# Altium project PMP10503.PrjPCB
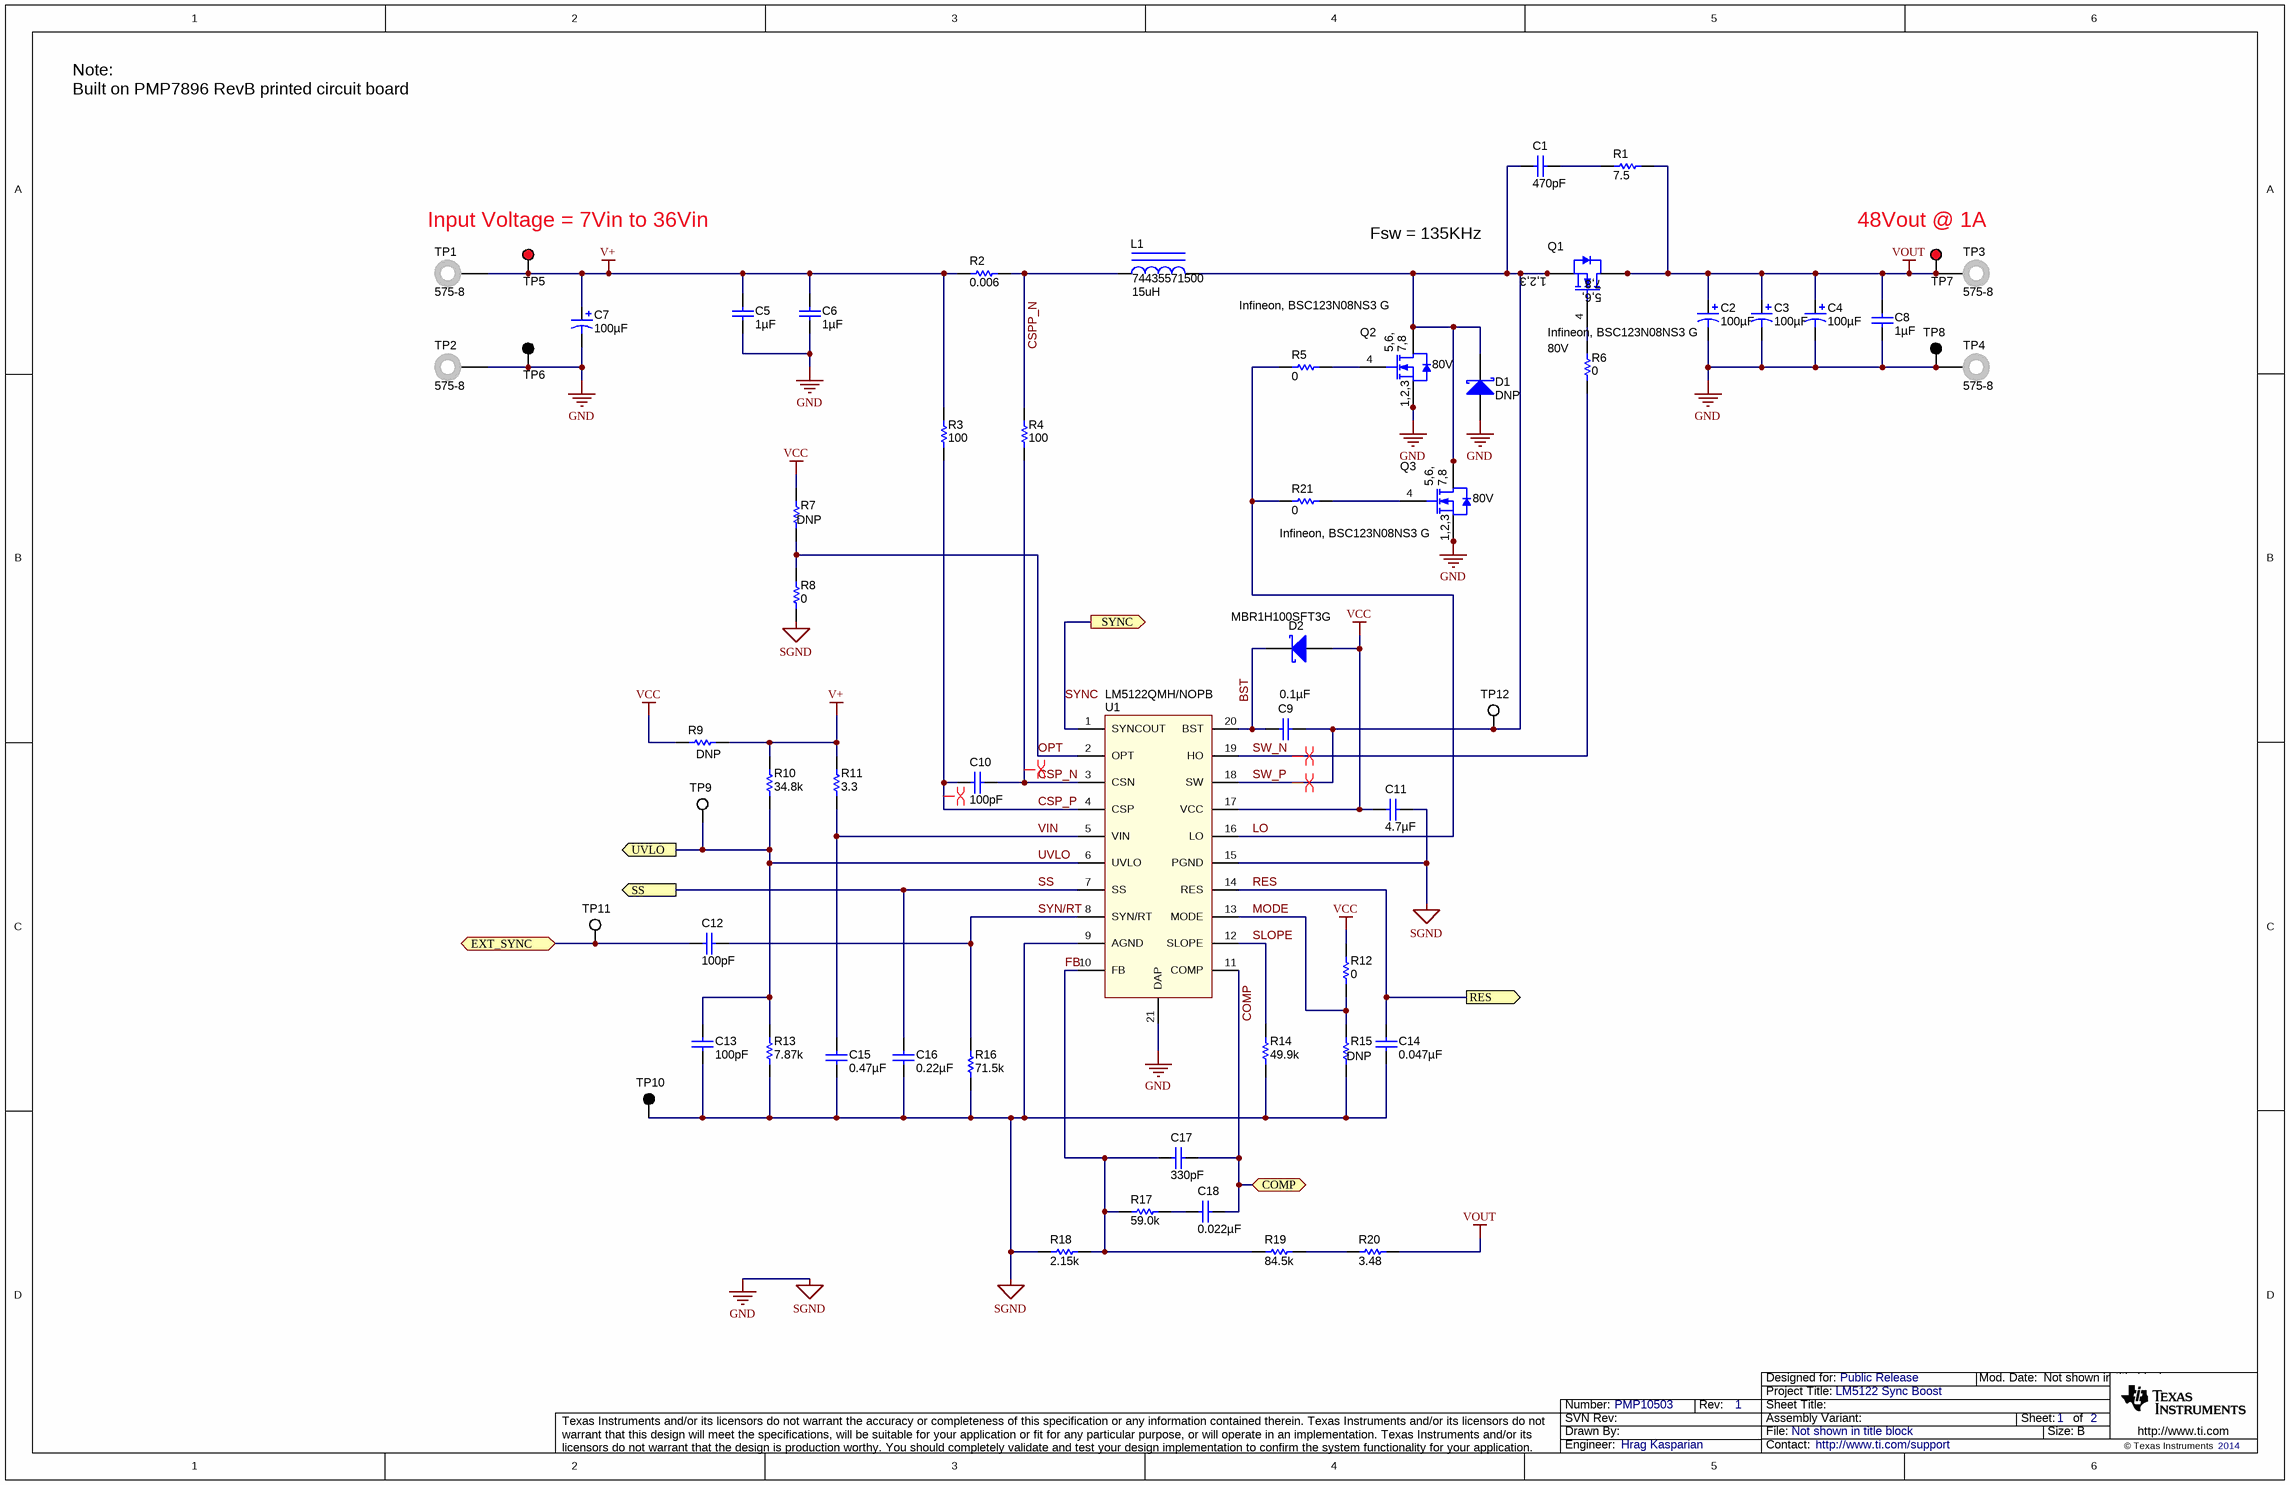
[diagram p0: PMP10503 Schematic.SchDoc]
TID: PMP10503; TechSupport: http://www.ti.com/support; SCH_Rev: 1; PRJ_Title: LM5122 Sync Boost; PRJ_Number: PMP10503; PRJ_Engineer: Hrag Kasparian; PRJ_Customer: Public Release; PCB_Rev: 1; PCB_Layout: Hrag Kasparian; CopyrightYear: 2014
2 sheets, 74 parts. Net scope: flat (ports and power ports of the same name join across sheets).
Board file: PMP7896 REVB.PcbDoc
Sheets:
  PMP10503 Schematic.SchDoc
  PMP10503_Hardware_ANSI-B.SchDoc

## Sheet PMP10503 Schematic.SchDoc
size 431 x 279 mm; Date: Not shown in title block; ApprovedBy: Not shown in title block; CheckedBy: Not shown in title block; Author: Not shown in title block; CompanyName: Not shown in title block; Engineer: Not shown in title block; Organization: Not shown in title block; Address1: Not shown in title block; Address2: Not shown in title block; Address3: Not shown in title block; Address4: Not shown in title block; DocumentNumber: 1; Revision: Use project parameter SCH_Rev; SheetNumber: 1; SheetTotal: 2; PageSetup: Record=PageOptions¦CenterHorizontal=True¦CenterVertical=True¦PrintScale=0.96¦XCorrection=1.00¦YCorrection=1.00¦PrintKind=0¦BorderSize=5000000¦LeftOffset=0¦BottomOffset=0¦Orientation=2¦PaperLength=1000¦PaperWidth=1000¦Scale=100¦PaperSource=15¦PrintQuality=600¦MediaType=1¦DitherType=10¦PaperKind=11x17¦PrintScaleMode=1

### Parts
C1  ValueDisplayed: 470pF  [0805_HV]  (hidden comment: GRM2165C2A471JA01D)
C2  ValueDisplayed: 100µF  [SM_RADIAL_J16]  (hidden comment: EEV-FK2A101M)
C3  ValueDisplayed: 100µF  [SM_RADIAL_J16]  (hidden comment: EEV-FK2A101M)
C4  ValueDisplayed: 100µF  [SM_RADIAL_J16]  (hidden comment: EEV-FK2A101M)
C5  ValueDisplayed: 1µF  [1206]  (hidden comment: C3216X7R2A105M)
C6  ValueDisplayed: 1µF  [1206]  (hidden comment: C3216X7R2A105M)
C7  ValueDisplayed: 100µF  [SM_RADIAL_J16]  (hidden comment: EMVH101GDA101MLH0S)
C8  ValueDisplayed: 1µF  [1206]  (hidden comment: C3216X7R2A105M)
C9  ValueDisplayed: 0.1µF  [0603]  (hidden comment: GRM188R72A104KA35D)
C10  ValueDisplayed: 100pF  [0603_HV]  (hidden comment: GRM1885C1H101JA01D)
C11  4.7µF  [0603_HV]
C12  ValueDisplayed: 100pF  [0603_HV]  (hidden comment: GRM1885C1H101JA01D)
C13  ValueDisplayed: 100pF  [0603_HV]  (hidden comment: GRM1885C1H101JA01D)
C14  ValueDisplayed: 0.047µF  [0603_HV]  (hidden comment: GRM188R71E473KA01D)
C15  ValueDisplayed: 0.47µF  [0805_HV]  (hidden comment: GRM21BR72A474KA73L)
C16  ValueDisplayed: 0.22µF  [0603]  (hidden comment: GRM188R71E224KA88D)
C17  ValueDisplayed: 330pF  [0603]  (hidden comment: C1608C0G1H331J)
C18  ValueDisplayed: 0.022µF  [0603]  (hidden comment: C1608X7R1H223K)
D1  DNP  [powerDI123]
D2  MBR1H100SFT3G  [SOD-123FL]
L1  74435571500  value 15uH  [WE-HCB_1890]
Q1  Infineon, BSC123N08NS3 G  value 80V  [PG-TDSON-8 WITH VIAS]
Q2  Infineon, BSC123N08NS3 G  value 80V  [PG-TDSON-8 WITH VIAS]
Q3  Infineon, BSC123N08NS3 G  value 80V  [PG-TDSON-8 WITH VIAS]
R1  value 7.5  [2010M]  (hidden comment: ERJ-12ZYJ7R5U)
R2  value 0.006  [2512M]  (hidden comment: ERJ-M1WSF6M0U)
R3  value 100  [0603]  (hidden comment: CRCW0603100RFKEA)
R4  value 100  [0603]  (hidden comment: CRCW0603100RFKEA)
R5  value 0  [0603_HV]  (hidden comment: ERJ-3GEY0R00V)
R6  value 0  [0603_HV]  (hidden comment: ERJ-3GEY0R00V)
R7  DNP  [0603]
R8  value 0  [0603_HV]  (hidden comment: ERJ-3GEY0R00V)
R9  DNP  [0603_HV]
R10  value 34.8k  [0603]  (hidden comment: CRCW060334K8FKEA)
R11  value 3.3  [0603_HV]  (hidden comment: CRCW06033R30JNEA)
R12  value 0  [0603_HV]  (hidden comment: ERJ-3GEY0R00V)
R13  value 7.87k  [0603]  (hidden comment: CRCW06037K87FKEA)
R14  value 49.9k  [0603]  (hidden comment: CRCW060349K9FKEA)
R15  DNP  [0603_HV]
R16  value 71.5k  [0603]  (hidden comment: CRCW060371K5FKEA)
R17  value 59.0k  [0603]  (hidden comment: CRCW060359K0FKEA)
R18  value 2.15k  [0603]  (hidden comment: CRCW06032K15FKEA)
R19  value 84.5k  [0603]  (hidden comment: CRCW060384K5FKEA)
R20  value 3.48  [0603]  (hidden comment: CRCW06033R48FKEA)
R21  value 0  [0603_HV]  (hidden comment: ERJ-3GEY0R00V)
TP1  575-8  [Keystone575-8]
TP2  575-8  [Keystone575-8]
TP3  575-8  [Keystone575-8]
TP4  575-8  [Keystone575-8]
TP5  5010  [Keystone5010]  (value not drawn)
TP6  5011  [Keystone5011]  (value not drawn)
TP7  5010  [Keystone5010]  (value not drawn)
TP8  5011  [Keystone5011]  (value not drawn)
TP9  5002  [Keystone5002]  (value not drawn)
TP10  5011  [Keystone5011]  (value not drawn)
TP11  5002  [Keystone5002]  (value not drawn)
TP12  5012  [Keystone5012]  (value not drawn)
U1  LM5122QMH/NOPB  [MXA20A_L]

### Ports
COMP, EXT_SYNC, RES, SS, SYNC (out), UVLO

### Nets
GND: C2.2(-) C3.2(-) C4.2(-) C5.2 C6.2 C7.2(-) C8.2 C11.1 C13.2 C14.2 C15.2 C16.2 D1.2(A) Q2.1(S) Q2.2(S) Q2.3(S) Q3.1(S) Q3.2(S) Q3.3(S) R8.1 R13.1 R14.1 R15.1 R16.1 R18.2 TP2.1 TP4.1 TP6.1 TP8.1 TP10.1 U1.9(AGND) U1.15(PGND) U1.21(DAP)  [also labelled SGND]
V+: C5.1 C6.1 C7.1(+) R2.1 R3.2 R9.1 R10.2 R11.2 TP1.1 TP5.1
VCC: C11.2 D2.2(A) R7.2 R9.2 R12.2 U1.17(VCC)
VOUT: C2.1(+) C3.1(+) C4.1(+) C8.1 Q1.5(D) Q1.6(D) Q1.7(D) Q1.8(D) Q1.9(D) R1.2 R20.1 TP3.1 TP7.1
BST: C9.2 D2.1(K) U1.20(BST)
COMP: C17.2 C18.2 U1.11(COMP) ; port COMP
CSP_N: C10.1 R4.1 U1.3(CSN)
CSP_P: C10.2 R3.1 U1.4(CSP)
CSPP_N: L1.1 R2.2 R4.2
EXT_SYNC: C12.2 TP11.1 ; port EXT_SYNC
FB: C17.1 R17.1 R18.1 R19.1 U1.10(FB)
LO: R5.2 R21.2 U1.16(LO)
MODE: R12.1 R15.2 U1.13(MODE)
OPT: R7.1 R8.2 U1.2(OPT)
RES: C14.1 U1.14(RES) ; port RES
SLOPE: R14.2 U1.12(SLOPE)
SS: C16.1 U1.7(SS) ; port SS
SW_N: R6.1 U1.19(HO)
SW_P: C1.2 C9.1 D1.1(K) L1.2 Q1.1(S) Q1.2(S) Q1.3(S) Q2.5(D) Q2.6(D) Q2.7(D) Q2.8(D) Q2.9(D) Q3.5(D) Q3.6(D) Q3.7(D) Q3.8(D) Q3.9(D) TP12.1 U1.18(SW)
SYN/RT: C12.1 R16.2 U1.8(SYN/RT)
SYNC: U1.1(SYNCOUT) ; port SYNC
UVLO: C13.1 R10.1 R13.2 TP9.1 U1.6(UVLO) ; port UVLO
VIN: C15.1 R11.1 U1.5(VIN)
NetC1_1: C1.1 R1.1
NetC18_1: C18.1 R17.2
NetQ1_4: Q1.4(G) R6.2
NetQ2_4: Q2.4(G) R5.1
NetQ3_4: Q3.4(G) R21.1
NetR19_2: R19.2 R20.2

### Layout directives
differential pair: CSP_N, CSP_P, SW_N, SW_P

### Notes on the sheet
- Note:
  Built on PMP7896 RevB printed circuit board
- Input Voltage = 7Vin to 36Vin
- Fsw = 135KHz
- 48Vout @ 1A

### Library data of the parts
C1 = GRM2165C2A471JA01D: CAP, CERM, 470pF, 100V, +/-5%, C0G/NP0, 0805; Manufacturer: MuRata; Polarized: N; CompType: Capacitor; U/M: EA; Cap_F: 0.00000000047; Tolerance_%: 5; VDC_V: 100; TaMin_C: -55; TaMax_C: 125; Cap_Case: 0805
C2-C4 = EEV-FK2A101M: CAP, AL, 100uF, 100V, +/-20%, 0.17 ohm, SMD; Manufacturer: Panasonic; Polarized: Y; CompType: Capacitor; U/M: EA; Cap_F: 0.0001; Tolerance_%: 20; VDC_V: 100; ESR_Ohm: 0.17; IRMS_A: 0.793; TaMin_C: -55; TaMax_C: 105; Cap_Case: J16
C5 C6 C8 = C3216X7R2A105M: CAP, CERM, 1uF, 100V, +/-20%, C Series, 1206; Manufacturer: TDK; Polarized: N; CompType: Capacitor; U/M: EA; Cap_F: 0.000001; Tolerance_%: 20; ESR_Ohm: 0.006; Value1: 0.006 ohm; VDC_V: 100; IRMS_A: 4.5; TaMin_C: -55; TaMax_C: 125
C7 = EMVH101GDA101MLH0S: CAP ALUM 100UF 100V 20% SMD; Manufacturer: United Chemi-Con; Polarized: Y; CompType: Capacitor; U/M: EA; Cap_F: 0.0001; Tolerance_%: 20; VDC_V: 100; IRMS_A: 0.44; TaMin_C: -40; TaMax_C: 85; Cap_Case: KE0
C9 = GRM188R72A104KA35D: CAP, CERM, 0.1uF, 100V, +/-10%, X7R, 0603; Manufacturer: MuRata; Polarized: N; CompType: Capacitor; U/M: EA; Cap_F: 0.0000001; Tolerance_%: 10; VDC_V: 100; TaMin_C: -55; TaMax_C: 125
C10 C12 C13 = GRM1885C1H101JA01D: CAP, CERM, 100pF, 50V, +/-5%, C0G/NP0, 0603; Manufacturer: MuRata; Polarized: N; CompType: Capacitor; U/M: EA; Cap_F: 0.0000000001; Tolerance_%: 5; VDC_V: 50; TaMin_C: -55; TaMax_C: 125; Cap_Case: 0603
C11 = C1608X6S1A475K: CAP CER 4.7UF 10V 10% X6S 0603; Manufacturer: TDK Corporation; CompType: Used in some BOM reports.  Useful for finding later.; SymbolVersion: use current date i.e. 2008-05-20; U/M: EA, IN, or GM; SymbolCreator: Use LDAP id
C14 = GRM188R71E473KA01D: CAP, CERM, 0.047uF, 25V, +/-10%, X7R, 0603; Manufacturer: MuRata; Polarized: N; CompType: Capacitor; U/M: EA; Cap_F: 0.000000047; Tolerance_%: 10; VDC_V: 25; TaMin_C: -55; TaMax_C: 125; Cap_Case: 0603
C15 = GRM21BR72A474KA73L: CAP, CERM, 0.47uF, 100V, +/-10%, X7R, 0805; Manufacturer: MuRata; Polarized: N; CompType: Capacitor; U/M: EA; Cap_F: 0.00000047; Tolerance_%: 10; VDC_V: 100; TaMin_C: -55; TaMax_C: 125; Cap_Case: 0805
C16 = GRM188R71E224KA88D: CAP, CERM, 0.22uF, 25V, +/-10%, X7R, 0603; Manufacturer: MuRata; Polarized: N; CompType: Capacitor; U/M: EA; Cap_F: 0.00000022; Tolerance_%: 10; Value1: Unknown; VDC_V: 25; TaMin_C: -55; TaMax_C: 125
C17 = C1608C0G1H331J: CAP, CERM, 330pF, 50V, +/-5%, C0G/NP0, 0603; Manufacturer: TDK; Polarized: N; CompType: Capacitor; U/M: EA; Cap_F: 0.00000000033; Tolerance_%: 5; ESR_Ohm: 0.1096; Value1: 0.1096 ohm; VDC_V: 50; TaMin_C: -55; TaMax_C: 125
C18 = C1608X7R1H223K: CAP, CERM, 0.022uF, 50V, +/-10%, X7R, 0603; Manufacturer: TDK; Polarized: N; CompType: Capacitor; U/M: EA; Cap_F: 0.000000022; Tolerance_%: 10; ESR_Ohm: 0.0383; Value1: 0.0383 ohm; VDC_V: 50; TaMin_C: -55; TaMax_C: 125
D1 = DFLS1100-7: Diode, Schottky, 100V, 1A, PowerDI123; Manufacturer: Diodes Inc.; Value: 0.77V; U/M: EA; Vf_V: 0.77; Io_A: 1; Vr_V: 100; TJmax_C: 175; RJC_CperW: 7
D2 = MBR1H100SFT3G: DIODE SCHOTTKY 1A 100V SOD-123FL; Manufacturer: On Semiconductor; U/M: EA; Vf_V: 0.57; Io_A: 1; Vr_V: 100; TJmax_C: 175; Value: 0.57V
L1 = 74435571500: Inductor, Shielded Drum Core, Ferrite, 15uH, 14A, 0.009 ohm, SMD; Manufacturer: Wurth Elektronik eiSos; ValueDisplayed: 15µH; Ind_H: 15.0E-6; Imax_A: 14; Irms: 14A @ 50C rise; Isat: 14A @ 30% inductance drop; DCR_ohm: 0.009
Q1-Q3 = BSC123N08NS3 G: MOSFET, N-CH, 80V, 55A, PG-TDSON-8; Manufacturer: Infineon Technologies; U/M: EA; ChType: N; VdsMax_V: 80; Value1: ? ohm; Value2: 19 nC; QgTyp_nC: 19; Vgs_V: 20; IdsMax_A: 55
R1 = ERJ-12ZYJ7R5U: RESISTOR 7.5 OHM 3/4W 5% 2010; Manufacturer: Panasonic; Value_Code: 7R50; Tolerance_%: 5; Power_W: 1; Value2: 1W; VDC_V: 3; TempCo: -100 /+600 ppm/C; EIA_Code: E24; U/M: EA
R2 = ERJ-M1WSF6M0U: RES, 0.006 ohm, 1%, 1W, 2512; Manufacturer: Panasonic; CompType: Resistor; Value_Code: R006; Tolerance_%: 1; TempCo: 100 ppm/C; EIA_Code: E96; U/M: EA
R3 R4 = CRCW0603100RFKEA: RES, 100 ohm, 1%, 0.1W, 0603; Manufacturer: Vishay-Dale; CompType: Resistor; Value_Code: 100R; Tolerance_%: 1; Power_W: 0.1; VDC_V: 75; TempCo: 100 ppm/C; EIA_Code: E96; U/M: EA
R5 R6 R8 R12 R21 = ERJ-3GEY0R00V: RES, 0 ohm, 5%, 0.1W, 0603; Manufacturer: Panasonic; CompType: Resistor; Value_Code: 0000; Tolerance_%: 5; Power_W: 0.1; VDC_V: 50; TempCo: 600 ppm/C; EIA_Code: E24; U/M: EA
R7 = CRCW0603158KFKEA: RES, 158k ohm, 1%, 0.1W, 0603; Manufacturer: Vishay-Dale; CompType: Resistor; Res_ohm: 158000; Tolerance_%: 1; Power_W: 0.1; VDC_V: 75; TempCo: 100 ppm/C; EIA_Code: E96; U/M: EA
R9 = CRCW06033R30JNEA: RES, 3.3 ohm, 5%, 0.1W, 0603; Manufacturer: Vishay-Dale; CompType: Resistor; Res_ohm: 3.3; Value_Code: 3R30; Tolerance_%: 5; Power_W: 0.1; VDC_V: 75; TempCo: 200 ppm/C; EIA_Code: E24; U/M: EA
R10 = CRCW060334K8FKEA: RES, 34.8k ohm, 1%, 0.1W, 0603; Manufacturer: Vishay-Dale; CompType: Resistor; Res_ohm: 34800; Value_Code: 34k8; Tolerance_%: 1; Power_W: 0.1; VDC_V: 75; TempCo: 100 ppm/C; EIA_Code: E96; U/M: EA
R11 = CRCW06033R30JNEA: RES, 3.3 ohm, 5%, 0.1W, 0603; Manufacturer: Vishay-Dale; CompType: Resistor; Value_Code: 3R30; Tolerance_%: 5; Power_W: 0.1; VDC_V: 75; TempCo: 200 ppm/C; EIA_Code: E24; U/M: EA
R13 = CRCW06037K87FKEA: RES, 7.87k ohm, 1%, 0.1W, 0603; Manufacturer: Vishay-Dale; CompType: Resistor; Res_ohm: 7870; Value_Code: 7k87; Tolerance_%: 1; Power_W: 0.1; VDC_V: 75; TempCo: 100 ppm/C; EIA_Code: E96; U/M: EA
R14 = CRCW060349K9FKEA: RES, 49.9k ohm, 1%, 0.1W, 0603; Manufacturer: Vishay-Dale; CompType: Resistor; Res_ohm: 49900; Value_Code: 49k9; Tolerance_%: 1; Power_W: 0.1; VDC_V: 75; TempCo: 100 ppm/C; EIA_Code: E96; U/M: EA
R15 = ERJ-3GEY0R00V: RES, 0 ohm, 5%, 0.1W, 0603; Manufacturer: Panasonic; CompType: Resistor; Res_ohm: 0; Value_Code: 0000; Tolerance_%: 5; Power_W: 0.1; VDC_V: 50; TempCo: 600 ppm/C; EIA_Code: E24; U/M: EA
R16 = CRCW060371K5FKEA: RES, 71.5k ohm, 1%, 0.1W, 0603; Manufacturer: Vishay-Dale; CompType: Resistor; Res_ohm: 71500; Value_Code: 71k5; Tolerance_%: 1; Power_W: 0.1; VDC_V: 75; TempCo: 100 ppm/C; EIA_Code: E96; U/M: EA
R17 = CRCW060359K0FKEA: RES, 59.0k ohm, 1%, 0.1W, 0603; Manufacturer: Vishay-Dale; CompType: Resistor; Res_ohm: 59000; Value_Code: 59k0; Tolerance_%: 1; Power_W: 0.1; VDC_V: 75; TempCo: 100 ppm/C; EIA_Code: E96; U/M: EA
R18 = CRCW06032K15FKEA: RES, 2.15k ohm, 1%, 0.1W, 0603; Manufacturer: Vishay-Dale; CompType: Resistor; Res_ohm: 2150; Value_Code: 2k15; Tolerance_%: 1; Power_W: 0.1; VDC_V: 75; TempCo: 100 ppm/C; EIA_Code: E96; U/M: EA
R19 = CRCW060384K5FKEA: RES, 84.5k ohm, 1%, 0.1W, 0603; Manufacturer: Vishay-Dale; CompType: Resistor; Res_ohm: 84500; Value_Code: 84k5; Tolerance_%: 1; Power_W: 0.1; VDC_V: 75; TempCo: 100 ppm/C; EIA_Code: E96; U/M: EA
R20 = CRCW06033R48FKEA: RES, 3.48 ohm, 1%, 0.1W, 0603; Manufacturer: Vishay-Dale; Alternate PartNumber: Equivalent; Alternate Manufacturer: Any; CompType: Resistor; Value_Code: 3R48; Tolerance_%: 1; Power_W: 0.1; VDC_V: 75; TempCo: 100 ppm/C; EIA_Code: E96; U/M: EA
TP1-TP4 = 575-8: Standard Banana Jack, Uninsulated, 8.9mm; Manufacturer: Keystone; Alternate Manufacturer: Any; Alternate PartNumber: Equivalent; CompType: Connector; U/M: EA
TP5 TP7 = 5010: Test Point, TH, Multipurpose, Red; Manufacturer: Keystone; Alternate Manufacturer: Any; Alternate PartNumber: Equivalent; CompType: Test Point Loop; U/M: EA
TP6 = 5011: Test Point, TH, Multipurpose, Black; Manufacturer: Keystone; Alternate Manufacturer: Any; Alternate PartNumber: Equivalent; CompType: Test Point Loop; U/M: EA
TP8 TP10 = 5011: Test Point, TH, Multipurpose, Black; Manufacturer: Keystone; CompType: Test Point Loop; U/M: EA
TP9 TP11 = 5002: Test Point, TH, Miniature, White; Manufacturer: Keystone; CompType: Test Point Loop; U/M: EA
TP12 = 5012: Test Point, TH, Multipurpose, White; Manufacturer: Keystone; Alternate Manufacturer: Any; Alternate PartNumber: Equivalent; CompType: Test Point Loop; U/M: EA
U1 = LM5122MH/NOPB: Wide Input Synchronous Boost Controller with Multiple Phase Capability, PWP0020A; Manufacturer: Texas Instruments; SymbolCreator: a0411947; CompType: IC; U/M: EA

## Sheet PMP10503_Hardware_ANSI-B.SchDoc
size 431 x 279 mm; Date: Not shown in title block; ApprovedBy: Not shown in title block; CheckedBy: Not shown in title block; Author: Not shown in title block; CompanyName: Not shown in title block; Engineer: Not shown in title block; Organization: Not shown in title block; Address1: Not shown in title block; Address2: Not shown in title block; Address3: Not shown in title block; Address4: Not shown in title block; DocumentNumber: 2; Revision: Use project parameter SCH_Rev; SheetNumber: 2; SheetTotal: 2; PageSetup: Record=PageOptions¦CenterHorizontal=True¦CenterVertical=True¦PrintScale=1.00¦XCorrection=1.00¦YCorrection=1.00¦PrintKind=0¦BorderSize=5000000¦LeftOffset=0¦BottomOffset=0¦Orientation=2¦PaperLength=1000¦PaperWidth=1000¦Scale=100¦PaperSource=15¦PrintQuality=600¦MediaType=1¦DitherType=10¦PaperKind=Letter¦PrintScaleMode=1
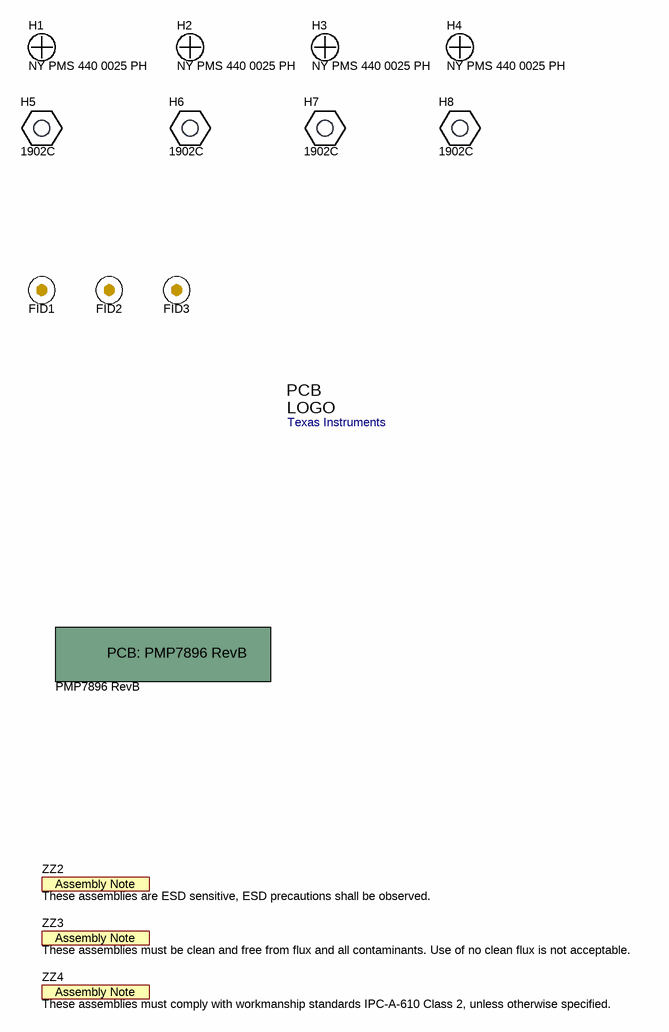
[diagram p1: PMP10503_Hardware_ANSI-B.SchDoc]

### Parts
!PCB?  PMP7896 RevB  (mechanical)
FID1  Fiducial  [Fiducial10-20]  (value not drawn)
FID2  Fiducial  [Fiducial10-20]  (value not drawn)
FID3  Fiducial  [Fiducial10-20]  (value not drawn)
H1  NY PMS 440 0025 PH  [NY PMS 440 0025 PH]
H2  NY PMS 440 0025 PH  [NY PMS 440 0025 PH]
H3  NY PMS 440 0025 PH  [NY PMS 440 0025 PH]
H4  NY PMS 440 0025 PH  [NY PMS 440 0025 PH]
H5  1902C  [Keystone_1902C]
H6  1902C  [Keystone_1902C]
H7  1902C  [Keystone_1902C]
H8  1902C  [Keystone_1902C]
Logo1  Texas Instruments  [TI_Stacked_SolderMask_Small]  (no BOM)
ZZ2  These assemblies are ESD sensitive, ESD precautions shall be observed.  [AssemblyNote]  (no BOM)
ZZ3  These assemblies must be clean and free from flux and all contaminants. Use of no clean flux is not acceptable.  [AssemblyNote]  (no BOM)
ZZ4  These assemblies must comply with workmanship standards IPC-A-610 Class 2, unless otherwise specified.  [AssemblyNote]  (no BOM)

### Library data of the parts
!PCB? = PCB_OtherProject: Manufacturer: Any; SymbolCreator: a0412235; CompType: PCB; U/M: EA
FID1-FID3 = Fiducial: Fiducial mark.  There is nothing to buy or mount.; SymbolCreator: codlsc
H1-H4 = NY PMS 440 0025 PH: Machine Screw, Round, #4-40 x 1/4, Nylon, Philips panhead; Manufacturer: B&F Fastener Supply; CompType: Hardware; SymbolCreator: codlsc; U/M: EA
H5-H8 = 1902C: Standoff, Hex, 0.5"L #4-40 Nylon; Manufacturer: Keystone; CompType: Hardware; SymbolCreator: a0412235
Logo1 = TI_Logo: Texas Instrument Corporate Signature; SymbolCreator: a0412235
ZZ2-ZZ4 = AssemblyNote: SymbolCreator: codlsc

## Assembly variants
001: not fitted D1 FID1 FID2 FID3 R7 R9 R15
